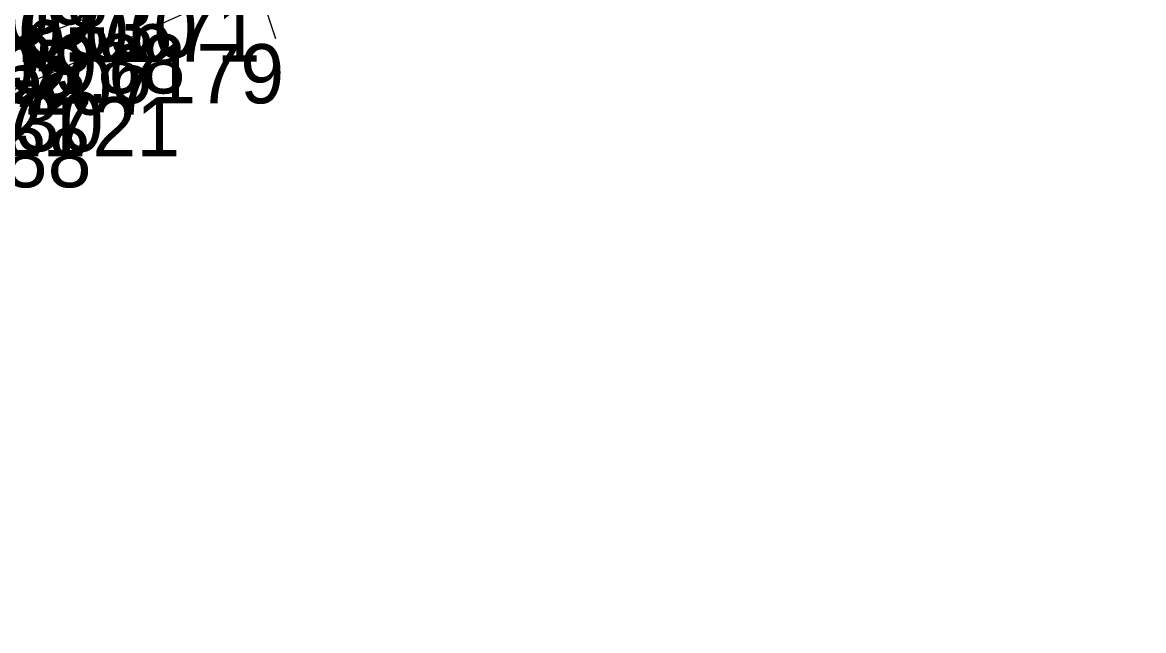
# Model space of a CAD drawing. Extents: x 1602514 to 1609837, y 863887 to 871157.
# Drawn here: x 1604666.7 to 1604810, y 865953.3 to 866031 of the extents above; entities that cross this region are included whole.
import ezdxf

# ---------------------------------------------------------------- set-up
doc = ezdxf.new("R2010")
doc.units = 0
for name, color, linetype in [('Default', 7, 'Continuous'), ('Survey-Point', 7, 'Continuous'), ('Survey-Text-Elevation', 7, 'Continuous'), ('Survey-Text-Feature', 7, 'Continuous')]:
    doc.layers.add(name, color=color, linetype=linetype)

msp = doc.modelspace()

# ---------------------------------------------------------------- linework, layer by layer
at = {"layer": 'Default'}
for points in [[(1604969.01, 866130.08), (1604947.53, 866114.66), (1604915.9, 866098.08), (1604878.31, 866083.75), (1604838.9, 866074.21), (1604795.51, 866067.39), (1604763.14, 866059.96), (1604741.7, 866054.99), (1604695.88, 866039.38), (1604651.97, 866023), (1604624.19, 866013.05), (1604572.23, 865989.52), (1604533.06, 865968.94), (1604507.4, 865954.89), (1604477.08, 865934.29), (1604465.98, 865925.57), (1604435.67, 865897.76)], [(1604969.01, 866130.08), (1604947.53, 866114.66), (1604915.9, 866098.08), (1604878.31, 866083.75), (1604838.9, 866074.21), (1604795.51, 866067.39), (1604763.14, 866059.96), (1604741.7, 866054.99), (1604695.88, 866039.38), (1604651.97, 866023), (1604624.19, 866013.05), (1604572.23, 865989.52), (1604533.06, 865968.94), (1604507.4, 865954.89), (1604477.08, 865934.29), (1604465.98, 865925.57), (1604435.67, 865897.76)], [(1604947.43, 866111.35), (1604916.99, 866095.23), (1604887.83, 866078.59), (1604869.51, 866073.57), (1604839.7, 866068.1), (1604796.01, 866064.89), (1604764.05, 866057.49), (1604744.43, 866051.86), (1604696.67, 866036.33), (1604655.01, 866017.68), (1604630.39, 866006.95), (1604577.01, 865980.66), (1604537.2, 865961.45), (1604527.45, 865955.57)], [(1604947.43, 866111.35), (1604916.99, 866095.23), (1604887.83, 866078.59), (1604869.51, 866073.57), (1604839.7, 866068.1), (1604796.01, 866064.89), (1604764.05, 866057.49), (1604744.43, 866051.86), (1604696.67, 866036.33), (1604655.01, 866017.68), (1604630.39, 866006.95), (1604577.01, 865980.66), (1604537.2, 865961.45), (1604527.45, 865955.57)]]:
    msp.add_lwpolyline(points, dxfattribs=at)
at = {"layer": 'Survey-Point'}
msp.add_line((1604699.08, 866028.9), (1604694.25, 866043.76), dxfattribs=at)

# ---------------------------------------------------------------- texts
at = {"layer": 'Survey-Text-Elevation'}
for s, p in [('767.3097', (1604639.19, 866028.05)), ('766.6830', (1604646.92, 866026.53)), ('770.0671', (1604654.97, 866026)), ('766.3988', (1604645.39, 866021.95)), ('766.1005', (1604631.65, 866021.26)), ('768.6179', (1604658.01, 866020.68)), ('767.3097', (1604627.19, 866016.05)), ('766.6830', (1604634.92, 866014.53)), ('766.3988', (1604633.39, 866009.95))]:
    msp.add_text(s, height=7.56, dxfattribs=at).set_placement(p)
at = {"layer": 'Survey-Text-Feature'}
for s, p in [('151', (1604660.78, 866029.57)), ('207', (1604654.97, 866019.22)), ('207', (1604666.97, 866019.22)), ('721', (1604658.01, 866013.9)), ('721', (1604670.01, 866013.9))]:
    msp.add_text(s, height=7.56, dxfattribs=at).set_placement(p)

doc.saveas('drawing.dxf')
